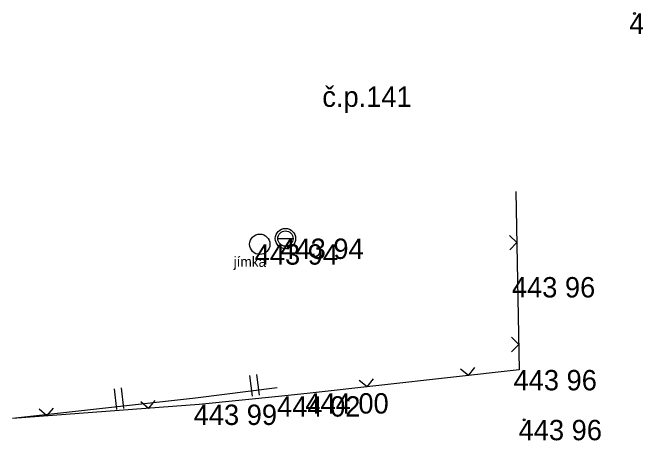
# Model space of a CAD drawing. Extents: x -554123 to -553118, y -1076825 to -1073672.
# Drawn here: x -553954.53 to -553923.95, y -1074643.95 to -1074622.94 of the extents above; entities that cross this region are included whole.
import ezdxf

# ---------------------------------------------------------------- set-up
doc = ezdxf.new("R2010")
doc.units = 0
for name, color, linetype in [('1', 7, 'Continuous'), ('12', 7, 'Continuous'), ('40', 7, 'Continuous'), ('52', 7, 'Continuous'), ('54', 7, 'Continuous'), ('6', 7, 'Continuous'), ('62', 7, 'Continuous')]:
    doc.layers.add(name, color=color, linetype=linetype)

# ---------------------------------------------------------------- blocks, each defined once
blk = doc.blocks.new('POINT_DISPLAY')
blk.add_line((0, 0), (0, 0))
blk = doc.blocks.new('T')
at = {"layer": '6'}
blk.add_circle((0, 0), 0.05, dxfattribs=at)
blk = doc.blocks.new('ST')
at = {"layer": '1'}
blk.add_line((-0.375, 0), (0.375, 0), dxfattribs=at)
blk.add_circle((0, 0), 0.375, dxfattribs=at)
blk = doc.blocks.new('ROV')
at = {"layer": '62'}
for p, q in [((-0.348, -0.51), (-0.348, 0.51)), ((0, -0.51), (0, 0.51))]:
    blk.add_line(p, q, dxfattribs=at)
blk = doc.blocks.new('SAK')
at = {"layer": '40'}
blk.add_circle((0, 0), 0.5, dxfattribs=at)

msp = doc.modelspace()

# ---------------------------------------------------------------- linework, layer by layer
at = {"layer": '12'}
for p, q in [((-553929.814, -1074631.735), (-553929.66, -1074640.49)), ((-553929.77, -1074634.235), (-553930.13, -1074633.887)), ((-553929.77, -1074634.235), (-553930.118, -1074634.595)), ((-553929.682, -1074639.234), (-553930.042, -1074638.886)), ((-553929.682, -1074639.234), (-553930.03, -1074639.594)), ((-553929.66, -1074640.49), (-553939.91, -1074641.63)), ((-553932.145, -1074640.766), (-553932.536, -1074640.454)), ((-553932.145, -1074640.766), (-553931.832, -1074640.375)), ((-553937.114, -1074641.319), (-553937.505, -1074641.006)), ((-553937.114, -1074641.319), (-553936.801, -1074640.928)), ((-553939.91, -1074641.63), (-553941.3, -1074641.78)), ((-553947.853, -1074642.375), (-553948.232, -1074642.048)), ((-553947.853, -1074642.375), (-553947.526, -1074641.996)), ((-553941.3, -1074641.78), (-553945.36, -1074642.19)), ((-553945.36, -1074642.19), (-553954.53, -1074642.87)), ((-553952.839, -1074642.745), (-553952.513, -1074642.365)), ((-553952.839, -1074642.745), (-553953.219, -1074642.418))]:
    msp.add_line(p, q, dxfattribs=at)
at = {"layer": '62'}
for p, q in [((-553941.53, -1074641.37), (-553945.55, -1074641.88)), ((-553945.55, -1074641.88), (-553954.53, -1074642.87))]:
    msp.add_line(p, q, dxfattribs=at)

# ---------------------------------------------------------------- block references
at = {"layer": '1'}
for name, p in [('POINT_DISPLAY', (-553924, -1074622.99)), ('ST', (-553941.13, -1074634.04)), ('POINT_DISPLAY', (-553941.13, -1074634.04)), ('POINT_DISPLAY', (-553941.13, -1074634.04)), ('POINT_DISPLAY', (-553942.39, -1074634.32)), ('POINT_DISPLAY', (-553929.74, -1074635.93)), ('POINT_DISPLAY', (-553929.66, -1074640.49)), ('POINT_DISPLAY', (-553939.91, -1074641.63)), ('POINT_DISPLAY', (-553941.3, -1074641.78)), ('POINT_DISPLAY', (-553945.36, -1074642.19)), ('POINT_DISPLAY', (-553929.41, -1074642.94))]:
    msp.add_blockref(name, p, dxfattribs=at)
at = {"layer": '40'}
for p in [(-553941.13, -1074634.04), (-553942.39, -1074634.32)]:
    msp.add_blockref('SAK', p, dxfattribs=at)
at = {"layer": '6'}
for p in [(-553924, -1074622.99), (-553929.41, -1074642.94)]:
    msp.add_blockref('T', p, dxfattribs=at)
at = {"layer": '62'}
for p, xscale, yscale, rotation in [((-553942.471, -1074641.225), 0.9999983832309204, 0.9999983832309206, 7.230384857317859), ((-553949.118, -1074641.881), 1.0000009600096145, 1.0000009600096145, 6.291075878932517)]:
    msp.add_blockref('ROV', p, dxfattribs=dict(at, xscale=xscale, yscale=yscale, rotation=rotation))

# ---------------------------------------------------------------- texts
at = {"layer": '52'}
msp.add_text('jímka', height=0.5, dxfattribs=at).set_placement((-553943.675, -1074635.427))
at = {"layer": '54'}
msp.add_text('č.p.141', height=1, dxfattribs=at).set_placement((-553939.32, -1074627.574))
at = {"layer": '6'}
for s, p in [('443 46 ', (-553924.25, -1074623.99)), ('443 94 ', (-553941.38, -1074635.04)), ('443 94 ', (-553941.38, -1074635.04)), ('443 94 ', (-553942.64, -1074635.32)), ('443 96 ', (-553930.014, -1074636.93)), ('443 96 ', (-553929.934, -1074641.49)), ('444 02 ', (-553941.54, -1074642.78)), ('444 00 ', (-553940.152, -1074642.63)), ('443 99 ', (-553945.634, -1074643.19)), ('443 96 ', (-553929.684, -1074643.94))]:
    msp.add_text(s, height=1, dxfattribs=at).set_placement(p)

doc.saveas('drawing.dxf')
